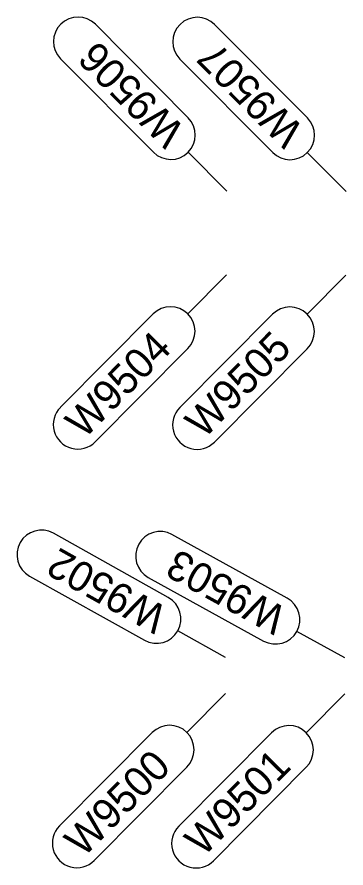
# Model space of a CAD drawing. Extents: x 12479652 to 12487250, y 9842710 to 9846560.
# Drawn here: x 12483663.74 to 12483677.53, y 9844325.05 to 9844360.69 of the extents above; entities that cross this region are included whole.
import ezdxf

# ---------------------------------------------------------------- set-up
doc = ezdxf.new("R2010")
doc.units = 0
doc.layers.add('Default', color=7, linetype='Continuous')

msp = doc.modelspace()

# ---------------------------------------------------------------- linework, layer by layer
at = {"layer": 'Default'}
for p, q in [((12483670.915, 9844356.472), (12483667.025, 9844360.385)), ((12483675.915, 9844356.46), (12483672.025, 9844360.374)), ((12483665.57, 9844358.939), (12483669.459, 9844355.026)), ((12483670.57, 9844358.927), (12483674.459, 9844355.014)), ((12483672.532, 9844353.39), (12483670.91, 9844355.021)), ((12483677.532, 9844353.378), (12483675.91, 9844355.01)), ((12483672.524, 9844349.89), (12483670.902, 9844348.259)), ((12483677.524, 9844349.878), (12483675.902, 9844348.247)), ((12483665.562, 9844344.342), (12483669.451, 9844348.254)), ((12483670.561, 9844344.33), (12483674.451, 9844348.243)), ((12483670.906, 9844346.808), (12483667.017, 9844342.895)), ((12483675.906, 9844346.796), (12483672.017, 9844342.883)), ((12483670.083, 9844336.377), (12483665.267, 9844339.068)), ((12483675.068, 9844336.351), (12483670.237, 9844339.014)), ((12483664.266, 9844337.277), (12483669.082, 9844334.586)), ((12483669.246, 9844337.217), (12483674.078, 9844334.554)), ((12483672.486, 9844333.858), (12483670.478, 9844334.981)), ((12483677.486, 9844333.847), (12483675.472, 9844334.957)), ((12483672.483, 9844332.358), (12483670.861, 9844330.727)), ((12483677.483, 9844332.347), (12483675.861, 9844330.715)), ((12483665.521, 9844326.81), (12483669.41, 9844330.723)), ((12483670.521, 9844326.798), (12483674.41, 9844330.711)), ((12483670.865, 9844329.276), (12483666.976, 9844325.364)), ((12483675.865, 9844329.265), (12483671.976, 9844325.352))]:
    msp.add_line(p, q, dxfattribs=at)
for centre, start, end in [((12483666.298, 9844359.662), 44.8253, 224.8253), ((12483671.298, 9844359.65), 44.8253, 224.8253), ((12483670.187, 9844355.749), 224.8253, 44.8253), ((12483675.187, 9844355.737), 224.8253, 44.8253), ((12483670.179, 9844347.531), 315.1702, 135.1702), ((12483675.179, 9844347.519), 315.1702, 135.1702), ((12483666.289, 9844343.618), 135.1702, 315.1702), ((12483671.289, 9844343.607), 135.1702, 315.1702), ((12483664.767, 9844338.173), 60.7981, 240.7981), ((12483669.741, 9844338.116), 61.1359, 241.1359), ((12483669.583, 9844335.481), 240.7981, 60.7981), ((12483674.573, 9844335.452), 241.1359, 61.1359), ((12483670.138, 9844330), 315.1702, 135.1702), ((12483675.138, 9844329.988), 315.1702, 135.1702), ((12483666.248, 9844326.087), 135.1702, 315.1702), ((12483671.248, 9844326.075), 135.1702, 315.1702)]:
    msp.add_arc(centre, 1.026, start, end, dxfattribs=at)

# ---------------------------------------------------------------- texts
for s, rotation, p in [('W9506', 134.8253, (12483670.841, 9844355.992)), ('W9507', 134.8253, (12483675.827, 9844355.994)), ('W9504', 45.1702, (12483666.554, 9844342.984)), ('W9505', 45.1702, (12483671.573, 9844342.991)), ('W9502', 150.7981, (12483670.116, 9844335.911)), ('W9503', 151.1359, (12483675.119, 9844335.877)), ('W9500', 45.1702, (12483666.519, 9844325.458)), ('W9501', 45.1702, (12483671.555, 9844325.483))]:
    msp.add_text(s, height=1.25, rotation=rotation, dxfattribs=at).set_placement(p)

doc.saveas('drawing.dxf')
